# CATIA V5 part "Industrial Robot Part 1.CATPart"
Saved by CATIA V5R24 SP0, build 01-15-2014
Part number: Industrial Robot Part 1
Source: Unknown
Material "Grey Blue": density 7860 kg/m3, Young's modulus 2e+11 Pa, Poisson ratio 0.266
Bounding box of the stored display mesh (mm): x -420 to 1700, y -800 to 1200, z 0 to 1399.142
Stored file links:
  C:\Users\cdl\Downloads\2024_CAD_final\p2\Industrial Robot Part 1.CATPart
  D:\Program Files\Dassault Systemes\B24\win_b64\startup\materials\Catalog.CATMaterial
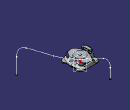
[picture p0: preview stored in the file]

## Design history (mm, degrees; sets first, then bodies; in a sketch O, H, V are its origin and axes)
Set1 "Center Point"
  Point1: (0, 0, 0)
  Sketch1 on xy-plane, origin (0, 0, 0), H (0, 1, 0), V (-1, 0, 0)
    point P1 (-800, 0)
    line L1 (-800, 0) -> (1200, 0)
    line L2 (1200, 0) -> (1200, -1700)
    line L3 (1200, -1700) -> (-800, -1700)
    line L4 (-800, -1700) -> (-800, 0)
    distance V L4 = 800
    length L1 = 2000
    length L2 = 1700
    coincidence: P1 H
    horizontal: L1 H, L3 H
    vertical: L2 V, L4 V
  Line1: type PtDir, RefPoint vertex [element of Sketch1 | element of Sketch1], Direction xy-plane, Start 0, End 1000
  Line2: type PtDir, RefPoint vertex [element of Sketch1 | element of Sketch1], Direction xy-plane, Start 0, End 1500
  Line3: type PtDir, RefPoint vertex [element of Sketch1 | element of Sketch1], Direction xy-plane, Start 0, End 700
  LineCorner1: Elements (vertex of Line1; vertex of Line2; vertex of Line3)
  Join1: Elements (Line1; LineCorner1; Line3)
  Corner1: Element1 Join1, Radius 500, Direction (0, 0, 1)
Body1 "Industrial Robot Part 1" (main body), material "Grey Blue"
  Solid1: solid without history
